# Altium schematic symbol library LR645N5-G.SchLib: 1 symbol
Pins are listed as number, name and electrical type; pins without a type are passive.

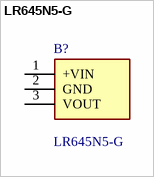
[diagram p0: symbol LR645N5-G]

## LR645N5-G
designator B?
Microchip LR645N5-G, Single Linear Voltage Regulator, 30mA Adjustable 9  11.5 V, 3-Pin TO-220; Geometry.Height: 4.826mm
footprint TO254P483X1016X2375-3P
pins: 1 +VIN, 2 GND, 3 VOUT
